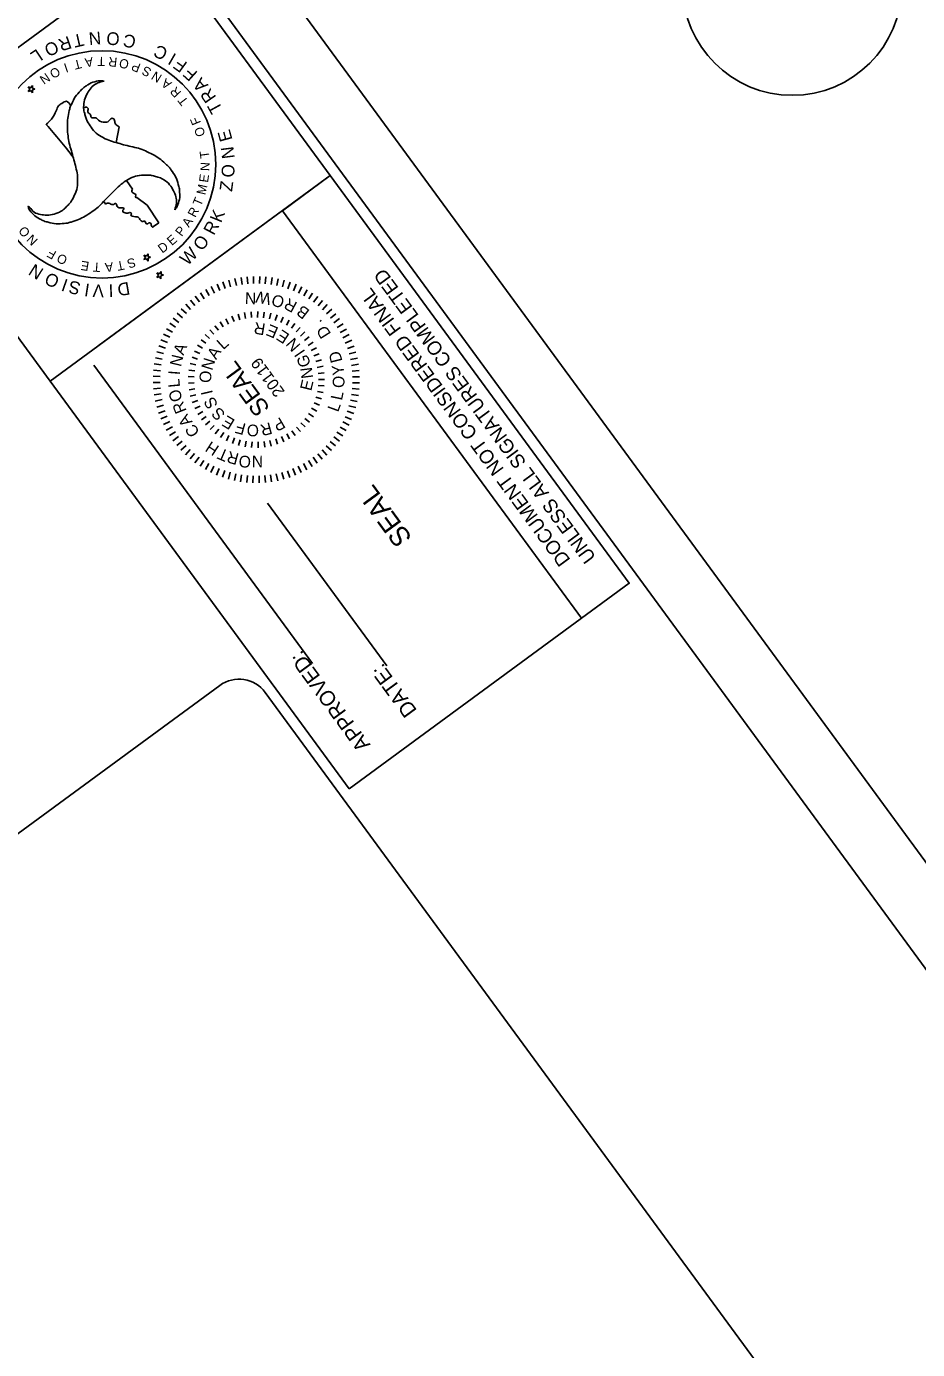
# Model space of a CAD drawing. Extents: x 719153 to 721402, y 581205 to 583188.
# Drawn here: x 720458.9 to 720670.5, y 582492.9 to 582807 of the extents above; entities that cross this region are included whole.
import ezdxf

# ---------------------------------------------------------------- set-up
doc = ezdxf.new("R2010")
doc.units = 0
for name, color, linetype in [('Old_Level_21', 7, 'Continuous'), ('Old_Level_50', 7, 'Continuous'), ('Old_Level_52', 7, 'Continuous'), ('Prop RDY Alternate Text Blue', 7, 'Continuous'), ('Scratch_Level_9', 7, 'Continuous'), ('Sheet Plot Border Inside CELL', 7, 'Continuous'), ('Sheet Plot Border Outside CELL', 7, 'Continuous'), ('Sheet Sticker Incomplete CELL', 7, 'Continuous'), ('Typical Terminator CELL', 7, 'Continuous')]:
    doc.layers.add(name, color=color, linetype=linetype)

msp = doc.modelspace()

# ---------------------------------------------------------------- linework, layer by layer
at = {"layer": 'Old_Level_21'}
for p, q in [((720519.64, 582763.23), (720531.01, 582771.57)), ((720531.01, 582771.57), (720602, 582674.8)), ((720590.64, 582666.46), (720519.64, 582763.23)), ((720602, 582674.8), (720590.64, 582666.46))]:
    msp.add_line(p, q, dxfattribs=at)
at = {"layer": 'Old_Level_50'}
msp.add_lwpolyline([(721009.35, 582149.27), (720410.24, 582965.86), (719878.1, 582575.44), (720477.21, 581758.85)], close=True, dxfattribs=at)
at = {"layer": 'Old_Level_52'}
msp.add_circle((720476.81, 582774.23), 26.98, dxfattribs=at)
at = {"layer": 'Scratch_Level_9'}
for p, q in [((720459.26, 582792.62), (720459.64, 582792.09)), ((720459.88, 582792.42), (720459.26, 582792.62)), ((720459.64, 582792.09), (720459.29, 582791.56)), ((720460.27, 582792.95), (720459.88, 582792.42)), ((720460.28, 582792.29), (720460.27, 582792.95)), ((720460.27, 582791.9), (720460.88, 582792.11)), ((720460.88, 582792.11), (720460.28, 582792.29)), ((720459.29, 582791.56), (720459.88, 582791.76)), ((720459.88, 582791.76), (720460.27, 582791.24)), ((720460.27, 582791.24), (720460.27, 582791.9)), ((720480.13, 582779.41), (720480.86, 582783.15)), ((720484.06, 582768.35), (720482.58, 582770.4)), ((720485.1, 582766.36), (720487.49, 582764.53)), ((720487.49, 582764.53), (720490.32, 582760.36)), ((720490.32, 582760.36), (720489.01, 582759.46)), ((720486.72, 582752.66), (720487.1, 582752.14)), ((720487.34, 582752.46), (720486.72, 582752.66)), ((720487.1, 582752.14), (720486.75, 582751.61)), ((720486.75, 582751.61), (720487.35, 582751.81)), ((720487.74, 582752.99), (720487.34, 582752.46)), ((720487.35, 582751.81), (720487.73, 582751.28)), ((720487.73, 582751.94), (720488.35, 582752.16)), ((720487.73, 582751.28), (720487.73, 582751.94)), ((720487.74, 582752.33), (720487.74, 582752.99)), ((720488.35, 582752.16), (720487.74, 582752.33)), ((720490.42, 582748.26), (720489.79, 582748.46)), ((720489.79, 582748.46), (720490.18, 582747.94)), ((720490.42, 582748.26), (720489.79, 582748.46)), ((720490.81, 582748.79), (720490.42, 582748.26)), ((720490.81, 582748.79), (720490.42, 582748.26)), ((720490.81, 582748.13), (720490.81, 582748.79)), ((720490.81, 582748.13), (720490.81, 582748.79)), ((720491.42, 582747.95), (720490.81, 582748.13)), ((720490.18, 582747.94), (720489.82, 582747.4)), ((720489.82, 582747.4), (720490.42, 582747.61)), ((720490.42, 582747.61), (720490.8, 582747.08)), ((720490.8, 582747.74), (720491.42, 582747.95)), ((720490.8, 582747.08), (720490.8, 582747.74))]:
    msp.add_line(p, q, dxfattribs=at)
for start, end in [(37.4702, 41.5902), (31.9452, 32.2429)]:
    msp.add_arc((720358.92, 582690.78), 139.92, start, end, dxfattribs=at)
for points in [[(720459.18, 582764.21), (720459.24, 582764.2), (720460.39, 582763.12), (720461.8, 582762.42), (720463.33, 582762.2), (720465, 582762.29), (720466.68, 582762.88), (720467.75, 582763.57), (720468.18, 582764.02), (720468.95, 582764.77), (720469.49, 582765.46), (720470.3, 582767), (720470.9, 582768.73), (720471, 582770.69), (720471, 582770.85), (720470.8, 582772.62), (720470.36, 582774.43), (720469.9, 582776.13), (720469.39, 582777.9), (720468.93, 582779.67), (720468.69, 582781.41), (720468.57, 582783.43), (720468.67, 582785.16), (720469.03, 582786.98), (720469.25, 582787.86), (720469.6, 582788.58), (720470.45, 582790.28), (720471.68, 582791.7), (720472.51, 582792.49), (720473.31, 582793.03), (720473.44, 582793.13), (720475.09, 582793.84), (720476.75, 582794.08), (720477.3, 582794.01)], [(720477.3, 582794.01), (720475.8, 582793.55), (720474.5, 582792.69), (720473.54, 582791.47), (720472.78, 582789.97), (720472.46, 582788.23), (720472.51, 582786.96), (720472.69, 582786.35), (720472.93, 582785.33), (720473.3, 582784.5), (720474.19, 582783.04), (720475.42, 582781.64), (720477.05, 582780.58), (720477.19, 582780.5), (720478.84, 582779.8), (720480.61, 582779.27), (720482.32, 582778.79), (720484.11, 582778.37), (720485.89, 582777.9), (720487.51, 582777.22), (720489.31, 582776.31), (720490.75, 582775.35), (720492.15, 582774.14), (720492.81, 582773.5), (720493.25, 582772.85), (720494.29, 582771.27), (720494.92, 582769.48), (720495.18, 582768.39), (720495.24, 582767.42), (720495.26, 582767.25), (720495.07, 582765.47), (720494.45, 582763.92), (720494.1, 582763.44)], [(720469.37, 582788.14), (720468.35, 582789.22), (720467.27, 582788.71), (720466.47, 582788.14), (720465.92, 582786.97), (720464.78, 582785), (720463.56, 582783.65)], [(720480.86, 582783.15), (720480.01, 582783.79), (720479.77, 582784.67), (720479.58, 582785.03), (720479.17, 582785.16), (720478.21, 582784.32), (720477.56, 582784.21), (720475.93, 582784.71), (720475.28, 582785.28), (720474.28, 582785.33), (720474.14, 582785.54), (720474.09, 582785.99), (720473.44, 582786.58), (720473.48, 582787.48), (720473.21, 582787.78), (720472.5, 582787.67)], [(720494.1, 582763.44), (720494.45, 582765), (720494.36, 582766.55), (720493.78, 582767.98), (720492.86, 582769.41), (720491.52, 582770.56), (720490.37, 582771.14), (720489.78, 582771.3), (720488.75, 582771.58), (720487.88, 582771.68), (720486.14, 582771.65), (720484.33, 582771.28), (720482.6, 582770.41), (720482.46, 582770.32), (720481.01, 582769.24), (720479.69, 582767.97), (720478.43, 582766.72), (720477.15, 582765.39), (720475.87, 582764.09), (720474.47, 582763.02), (720472.78, 582761.92), (720471.22, 582761.14), (720469.46, 582760.54), (720468.6, 582760.3), (720467.81, 582760.23), (720465.9, 582760.13), (720464.05, 582760.48), (720462.97, 582760.8), (720462.11, 582761.22), (720461.96, 582761.29), (720460.5, 582762.35), (720459.46, 582763.66), (720459.24, 582764.2)], [(720484.06, 582768.35), (720483.87, 582767.95), (720484.01, 582767.55), (720484.58, 582767.27), (720484.81, 582766.94), (720484.8, 582766.37), (720485.1, 582766.36)], [(720489.01, 582759.46), (720488.91, 582759.33), (720488.62, 582759.45), (720488.42, 582760.23), (720487.94, 582760.34), (720487.69, 582760.14), (720487.25, 582760.19), (720487.03, 582760.66), (720486.3, 582760.69), (720485.95, 582760.96), (720485.42, 582761.69), (720483.93, 582761.92), (720483.61, 582762.23), (720483.77, 582762.5), (720483.65, 582762.75), (720482.66, 582762.61), (720482.5, 582762.63), (720481.74, 582763.09), (720481.75, 582763.37), (720482.02, 582763.65), (720482, 582763.79), (720481.69, 582763.9), (720481.09, 582763.92), (720480.4, 582764.25), (720480.02, 582764.94), (720479.42, 582764.67), (720478.39, 582765.05), (720477.98, 582764.98), (720477.65, 582764.8)]]:
    msp.add_spline(points, degree=3, dxfattribs=at)
at = {"layer": 'Sheet Plot Border Inside CELL'}
msp.add_lwpolyline([(719899.07, 582572.22), (720431.46, 581846.57), (720939.41, 582219.25), (720407.02, 582944.89)], close=True, dxfattribs=at)
at = {"layer": 'Sheet Plot Border Outside CELL'}
for p, q in [((720475.86, 582731.11), (720531, 582771.57)), ((720526.81, 582655.76), (720474.87, 582726.55)), ((720544.4, 582655.18), (720516.08, 582693.78))]:
    msp.add_line(p, q, dxfattribs=at)
for points in [[(720340.26, 582892.08), (720424.03, 582777.92), (720490.54, 582826.72), (720406.78, 582940.89)], [(720464.49, 582722.76), (720424.03, 582777.92), (720490.54, 582826.72), (720531.01, 582771.57)], [(720535.49, 582625.99), (720464.49, 582722.76), (720531.01, 582771.57), (720602, 582674.8)]]:
    msp.add_lwpolyline(points, close=True, dxfattribs=at)
msp.add_circle((720640.7, 582816.63), 26.01, dxfattribs=at)
at = {"layer": 'Sheet Sticker Incomplete CELL'}
for p, q in [((720116.85, 582365.91), (720504.77, 582650.51)), ((720818.48, 582236), (720515.57, 582648.85))]:
    msp.add_line(p, q, dxfattribs=at)
msp.add_arc((720509.34, 582644.28), 7.73, 36.2666, 126.2666, dxfattribs=at)
at = {"layer": 'Typical Terminator CELL'}
for p, q in [((720502.76, 582745.2), (720503.48, 582743.69)), ((720504.11, 582745.8), (720504.75, 582744.26)), ((720505.5, 582746.33), (720506.04, 582744.74)), ((720506.91, 582746.76), (720507.35, 582745.15)), ((720508.35, 582747.11), (720508.7, 582745.48)), ((720509.81, 582747.38), (720510.06, 582745.72)), ((720511.28, 582747.55), (720511.43, 582745.89)), ((720512.76, 582747.64), (720512.8, 582745.97)), ((720514.24, 582747.63), (720514.18, 582745.96)), ((720515.72, 582747.54), (720515.56, 582745.88)), ((720517.19, 582747.36), (720516.93, 582745.71)), ((720518.64, 582747.09), (720518.29, 582745.46)), ((720520.08, 582746.73), (720519.63, 582745.12)), ((720521.5, 582746.29), (720520.95, 582744.71)), ((720522.88, 582745.76), (720522.24, 582744.22)), ((720524.23, 582745.15), (720523.49, 582743.65)), ((720497.78, 582742), (720498.85, 582740.71)), ((720498.95, 582742.91), (720499.94, 582741.56)), ((720500.17, 582743.75), (720501.08, 582742.34)), ((720501.44, 582744.51), (720502.26, 582743.06)), ((720525.54, 582744.45), (720524.71, 582743)), ((720526.81, 582743.69), (720525.9, 582742.28)), ((720528.02, 582742.84), (720527.03, 582741.5)), ((720529.19, 582741.93), (720528.11, 582740.65)), ((720494.64, 582738.87), (720495.92, 582737.79)), ((720495.62, 582739.97), (720496.84, 582738.83)), ((720496.67, 582741.02), (720497.81, 582739.8)), ((720509.14, 582738.7), (720509.51, 582737.36)), ((720510.66, 582739.04), (720510.9, 582737.67)), ((720512.21, 582739.24), (720512.32, 582737.85)), ((720513.77, 582739.28), (720513.74, 582737.89)), ((720515.33, 582739.17), (720515.17, 582737.79)), ((720516.87, 582738.92), (720516.57, 582737.56)), ((720530.29, 582740.94), (720529.15, 582739.73)), ((720531.34, 582739.89), (720530.12, 582738.75)), ((720532.32, 582738.78), (720531.03, 582737.71)), ((720492.88, 582736.49), (720494.28, 582735.58)), ((720493.72, 582737.7), (720495.07, 582736.71)), ((720503.58, 582735.93), (720504.43, 582734.83)), ((720504.86, 582736.82), (720505.6, 582735.64)), ((720506.8, 582736.32), (720506.18, 582737.56)), ((720507.65, 582738.22), (720508.15, 582736.92)), ((720518.38, 582738.51), (720517.95, 582737.19)), ((720519.84, 582737.97), (720519.29, 582736.68)), ((720521.24, 582737.28), (720520.57, 582736.06)), ((720522.58, 582736.46), (720521.79, 582735.31)), ((720523.82, 582735.51), (720522.92, 582734.44)), ((720533.23, 582737.61), (720531.88, 582736.62)), ((720534.07, 582736.39), (720532.66, 582735.48)), ((720490.8, 582732.56), (720492.35, 582731.92)), ((720491.42, 582733.91), (720492.92, 582733.17)), ((720492.11, 582735.22), (720493.56, 582734.39)), ((720500.33, 582732.57), (720501.46, 582731.76)), ((720501.3, 582733.8), (720502.35, 582732.88)), ((720502.39, 582734.92), (720503.34, 582733.9)), ((720524.97, 582734.46), (720523.97, 582733.48)), ((720526.01, 582733.29), (720524.92, 582732.42)), ((720534.83, 582735.12), (720533.37, 582734.3)), ((720535.52, 582733.81), (720534.01, 582733.08)), ((720536.12, 582732.46), (720534.58, 582731.82)), ((720489.83, 582729.76), (720491.44, 582729.31)), ((720490.28, 582731.18), (720491.85, 582730.63)), ((720498.76, 582729.88), (720500.02, 582729.3)), ((720499.48, 582731.27), (720500.68, 582730.56)), ((720526.93, 582732.03), (720525.77, 582731.26)), ((720527.73, 582730.69), (720526.5, 582730.04)), ((720527.1, 582728.74), (720528.4, 582729.26)), ((720536.65, 582731.07), (720535.06, 582730.53)), ((720537.08, 582729.65), (720535.47, 582729.21)), ((720489.21, 582726.87), (720490.86, 582726.61)), ((720489.47, 582728.32), (720491.11, 582727.97)), ((720497.73, 582726.93), (720499.09, 582726.6)), ((720498.17, 582728.43), (720499.49, 582727.97)), ((720528.91, 582727.8), (720527.58, 582727.4)), ((720529.29, 582726.29), (720527.92, 582726.01)), ((720537.43, 582728.21), (720535.8, 582727.87)), ((720537.7, 582726.76), (720536.04, 582726.51)), ((720488.93, 582723.92), (720490.6, 582723.87)), ((720489.02, 582725.4), (720490.69, 582725.24)), ((720497.29, 582723.84), (720498.69, 582723.78)), ((720497.44, 582725.4), (720498.82, 582725.2)), ((720529.52, 582724.74), (720528.14, 582724.6)), ((720529.6, 582723.18), (720528.21, 582723.18)), ((720537.87, 582725.28), (720536.21, 582725.14)), ((720537.96, 582723.81), (720536.29, 582723.76)), ((720488.93, 582722.44), (720490.6, 582722.48)), ((720489.01, 582720.96), (720490.68, 582721.11)), ((720497.3, 582722.28), (720498.69, 582722.35)), ((720497.46, 582720.73), (720498.83, 582720.93)), ((720529.32, 582720.08), (720527.95, 582720.34)), ((720529.54, 582721.62), (720528.15, 582721.75)), ((720537.86, 582720.85), (720536.2, 582721)), ((720537.95, 582722.33), (720536.28, 582722.38)), ((720489.19, 582719.49), (720490.84, 582719.74)), ((720489.45, 582718.03), (720491.09, 582718.38)), ((720489.8, 582716.59), (720491.41, 582717.04)), ((720497.76, 582719.2), (720499.11, 582719.53)), ((720498.21, 582717.7), (720499.53, 582718.17)), ((720498.81, 582716.26), (720500.07, 582716.85)), ((720528.43, 582717.08), (720527.14, 582717.6)), ((720528.95, 582718.56), (720527.61, 582718.95)), ((720537.05, 582716.48), (720535.44, 582716.93)), ((720537.41, 582717.92), (720535.78, 582718.27)), ((720537.68, 582719.38), (720536.03, 582719.63)), ((720490.24, 582715.18), (720491.82, 582715.72)), ((720490.76, 582713.79), (720492.31, 582714.43)), ((720499.54, 582714.88), (720500.74, 582715.59)), ((720500.4, 582713.57), (720501.52, 582714.4)), ((720501.52, 582714.4), (720500.4, 582713.57)), ((720526.08, 582713.05), (720524.99, 582713.92)), ((720527, 582714.32), (720525.83, 582715.07)), ((720527.78, 582715.66), (720526.55, 582716.31)), ((720536.08, 582713.68), (720534.54, 582714.33)), ((720536.61, 582715.07), (720535.03, 582715.62)), ((720491.37, 582712.44), (720492.87, 582713.17)), ((720492.05, 582711.12), (720493.51, 582711.94)), ((720492.82, 582709.85), (720494.22, 582710.76)), ((720501.38, 582712.36), (720502.42, 582713.29)), ((720502.48, 582711.25), (720503.42, 582712.27)), ((720503.67, 582710.24), (720504.52, 582711.35)), ((720504.96, 582709.36), (720505.7, 582710.55)), ((720522.67, 582709.85), (720521.88, 582711)), ((720523.91, 582710.81), (720523.01, 582711.87)), ((720525.05, 582711.88), (720524.05, 582712.84)), ((720534.01, 582709.76), (720532.6, 582710.67)), ((720534.77, 582711.03), (720533.32, 582711.85)), ((720535.47, 582712.33), (720533.97, 582713.07)), ((720493.65, 582708.63), (720495, 582709.62)), ((720494.57, 582707.46), (720495.85, 582708.53)), ((720495.55, 582706.35), (720496.77, 582707.49)), ((720506.33, 582708.61), (720506.95, 582709.86)), ((720507.77, 582707.99), (720508.26, 582709.29)), ((720509.25, 582707.51), (720509.62, 582708.86)), ((720510.78, 582707.18), (720511.01, 582708.55)), ((720512.33, 582707), (720512.43, 582708.39)), ((720513.89, 582706.96), (720513.86, 582708.36)), ((720515.45, 582707.08), (720515.28, 582708.47)), ((720516.99, 582707.35), (720516.68, 582708.71)), ((720518.49, 582707.77), (720518.06, 582709.09)), ((720519.95, 582708.33), (720519.39, 582709.6)), ((720521.35, 582709.03), (720520.67, 582710.24)), ((720531.26, 582706.27), (720530.05, 582707.42)), ((720532.24, 582707.38), (720530.97, 582708.45)), ((720533.16, 582708.54), (720531.82, 582709.54)), ((720496.59, 582705.3), (720497.74, 582706.52)), ((720497.7, 582704.32), (720498.77, 582705.6)), ((720498.86, 582703.4), (720499.86, 582704.75)), ((720527.93, 582703.33), (720526.94, 582704.68)), ((720529.1, 582704.25), (720528.03, 582705.53)), ((720530.21, 582705.23), (720529.07, 582706.45)), ((720500.08, 582702.56), (720500.99, 582703.96)), ((720501.34, 582701.79), (720502.17, 582703.24)), ((720502.65, 582701.1), (720503.39, 582702.6)), ((720504, 582700.48), (720504.65, 582702.03)), ((720505.39, 582699.96), (720505.94, 582701.54)), ((720506.8, 582699.51), (720507.25, 582701.12)), ((720519.97, 582699.48), (720519.53, 582701.09)), ((720521.39, 582699.92), (720520.84, 582701.5)), ((720522.78, 582700.44), (720522.14, 582701.99)), ((720524.13, 582701.05), (720523.4, 582702.55)), ((720525.44, 582701.73), (720524.62, 582703.19)), ((720526.71, 582702.5), (720525.8, 582703.9)), ((720508.24, 582699.16), (720508.59, 582700.79)), ((720509.7, 582698.89), (720509.95, 582700.54)), ((720511.17, 582698.7), (720511.32, 582700.37)), ((720512.65, 582698.61), (720512.7, 582700.28)), ((720514.13, 582698.61), (720514.08, 582700.28)), ((720515.6, 582698.69), (720515.46, 582700.36)), ((720517.08, 582698.87), (720516.83, 582700.52)), ((720518.53, 582699.13), (720518.19, 582700.77))]:
    msp.add_line(p, q, dxfattribs=at)

# ---------------------------------------------------------------- texts
at = {"layer": 'Old_Level_21'}
for s, p in [('UNLESS ALL SIGNATURES COMPLETED', (720594.22, 582680.99)), ('DOCUMENT NOT CONSIDERED FINAL', (720588.16, 582680.32))]:
    msp.add_text(s, height=3.3, rotation=126.2667, dxfattribs=at).set_placement(p)
at = {"layer": 'Old_Level_52'}
for s, rotation, p in [('R', 199.0185, (720468.89, 582804.77)), ('T', 193.1477, (720472.05, 582805.42)), ('N', 185.1586, (720476.43, 582805.78)), ('O', 176.7193, (720481.07, 582805.49)), ('C', 169.3474, (720485.05, 582804.69)), ('L', 213.6957, (720461.41, 582801.77)), ('O', 205.2563, (720465.61, 582803.73)), ('C', 154.27, (720492.69, 582801.5)), ('I', 150.0169, (720494.67, 582800.25)), ('F', 144.0293, (720497.28, 582798.24)), ('F', 138.0417, (720499.68, 582795.97)), ('A', 131.0701, (720502.15, 582793.04)), ('R', 124.8323, (720504.04, 582790.17)), ('T', 118.9615, (720505.53, 582787.31)), ('E', 105.2183, (720507.81, 582780.11)), ('N', 97.2293, (720508.33, 582775.74)), ('O', 88.79, (720508.21, 582771.1)), ('Z', 82.4354, (720507.67, 582767.64)), ('R', 61.8207, (720503.38, 582757.2)), ('K', 68.0585, (720505.07, 582760.19)), ('W', 44.4167, (720497.07, 582750.03)), ('O', 53.3814, (720500.59, 582753.48))]:
    msp.add_text(s, height=3.02, rotation=rotation, dxfattribs=at).set_placement(p)
at = {"layer": 'Prop RDY Alternate Text Blue'}
msp.add_text('SEAL', height=4.687, rotation=126.2667, dxfattribs=at).set_placement((720550.6, 582685.58))
at = {"layer": 'Scratch_Level_9'}
for s, height, rotation, p in [('T', 2.18, 193.9593, (720471.62, 582799.24)), ('A', 2.18, 188.8812, (720474.51, 582799.7)), ('T', 2.18, 178.725, (720477.56, 582799.74)), ('R', 2.18, 173.647, (720480.52, 582799.5)), ('O', 2.18, 168.5689, (720483.35, 582798.95)), ('N', 2.18, 213.9996, (720463.52, 582796.06)), ('O', 2.18, 209.1936, (720466.1, 582797.48)), ('I', 2.18, 199.0374, (720468.3, 582798.29)), ('P', 2.18, 158.4127, (720486.16, 582797.98)), ('S', 2.18, 153.3346, (720488.74, 582796.8)), ('N', 2.18, 148.2565, (720491.22, 582795.33)), ('A', 2.18, 143.1785, (720493.51, 582793.61)), ('R', 2.18, 133.0223, (720495.76, 582791.34)), ('T', 2.18, 127.9442, (720497.46, 582789.25)), ('F', 2.18, 112.7099, (720500.35, 582784.11)), ('O', 2.18, 107.6319, (720501.38, 582781.2)), ('T', 2.18, 97.4757, (720502.35, 582775.8)), ('N', 2.18, 87.3195, (720502.29, 582772.6)), ('E', 2.18, 82.2414, (720501.97, 582769.82)), ('M', 2.18, 77.1634, (720501.31, 582766.85)), ('R', 2.18, 61.9291, (720498.94, 582761.47)), ('T', 2.18, 67.0072, (720500.26, 582764.13)), ('A', 2.18, 56.851, (720497.44, 582759.12)), ('O', 2.18, 130.2112, (720459.91, 582758.05)), ('N', 2.18, 135.2893, (720461.73, 582756.3)), ('E', 2.18, 41.6168, (720493.4, 582754.82)), ('P', 2.18, 51.7729, (720495.7, 582756.96)), ('D', 2.18, 36.5387, (720491.09, 582753.03)), ('F', 2.18, 150.5236, (720466.16, 582753.43)), ('O', 2.18, 155.6017, (720468.79, 582752.22)), ('E', 2.18, 170.8359, (720473.88, 582751.04)), ('T', 2.18, 191.1483, (720481.86, 582751.42)), ('S', 2.18, 196.2263, (720484.43, 582752.12)), ('N', 3.02, 147.8527, (720463.16, 582749.22)), ('O', 3.02, 156.3601, (720466.96, 582747.46)), ('T', 2.18, 175.914, (720476.5, 582750.84)), ('A', 2.18, 186.0702, (720479.34, 582751.01)), ('I', 3.02, 160.6475, (720468.96, 582746.79)), ('S', 3.02, 166.8515, (720471.94, 582746.1)), ('I', 3.02, 171.1388, (720474.03, 582745.8)), ('V', 3.02, 177.8473, (720477.33, 582745.66)), ('I', 3.02, 182.1346, (720479.44, 582745.78)), ('D', 3.02, 189.7257, (720483.13, 582746.36))]:
    msp.add_text(s, height=height, rotation=rotation, dxfattribs=at).set_placement(p)
at = {"layer": 'Sheet Plot Border Outside CELL'}
for s, p in [('APPROVED:  ', (720540.65, 582636.46)), ('DATE:  ', (720551.73, 582644.59))]:
    msp.add_text(s, height=3.6, rotation=126.2667, dxfattribs=at).set_placement(p)
at = {"layer": 'Typical Terminator CELL'}
for s, height, rotation, p in [('N', 2.78, 178.4207, (720513.46, 582743.78)), ('W', 2.78, 169.5381, (720517.1, 582743.55)), ('O', 2.78, 160.6554, (720520.4, 582742.58)), ('R', 2.78, 151.8328, (720523.38, 582741.33)), ('B', 2.78, 142.8303, (720526.3, 582739.48)), ('R', 2.78, 170.7785, (720515.76, 582736.38)), ('E', 2.78, 157.0075, (720518.89, 582735.38)), ('D', 2.78, 122.3036, (720531.28, 582734)), ('.', 2.78, 130.046, (720529.22, 582736.84)), ('L', 2.78, 42.0843, (720505.58, 582730.08)), ('E', 2.78, 147.0216, (720521.54, 582733.78)), ('N', 2.78, 131.6295, (720524.12, 582731.3)), ('A', 2.78, 66.7307, (720496.12, 582728.75)), ('A', 2.78, 57.3805, (720503.89, 582727.73)), ('I', 2.78, 123.9998, (720525.16, 582729.72)), ('D', 2.78, 104.5083, (720533.91, 582727.53)), ('N', 2.78, 76.4983, (720495.55, 582726.05)), ('N', 2.78, 72.6768, (720502.95, 582725.15)), ('SEAL', 4.179, 126.2136, (720516.85, 582716.34)), ('20119', 2.784, 126.2136, (720520.31, 582720.29)), ('G', 2.78, 105.905, (720526.4, 582726.52)), ('Y', 2.78, 95.5358, (720534.35, 582724.27)), ('L', 2.78, 95.3682, (720495.34, 582721.38)), ('I', 2.78, 85.7927, (720495.31, 582724.15)), ('O', 2.78, 87.973, (720502.71, 582722.32)), ('E', 2.78, 76.2837, (720526.47, 582720.3)), ('N', 2.78, 97.1388, (720526.96, 582723.55)), ('O', 2.78, 86.8632, (720534.29, 582721.08)), ('O', 2.78, 108.5045, (720496.01, 582718.37)), ('I', 2.78, 103.2693, (720503.16, 582719.86)), ('L', 2.78, 78.2205, (720533.77, 582718.07)), ('R', 2.78, 111.5613, (720496.96, 582715.72)), ('S', 2.78, 118.5655, (720504.43, 582717.12)), ('L', 2.78, 70.1487, (720532.86, 582715.27)), ('A', 2.78, 123.5706, (720498.37, 582713.09)), ('S', 2.78, 133.8618, (720506.26, 582715.02)), ('E', 2.78, 149.158, (720508.57, 582713.47)), ('P', 2.78, 210.343, (720519.21, 582714.32)), ('C', 2.78, 123.5706, (720500.12, 582710.61)), ('F', 2.78, 164.4543, (720511.16, 582712.6)), ('O', 2.78, 179.7505, (720514.07, 582712.44)), ('R', 2.78, 195.0468, (720516.73, 582713.03)), ('H', 2.78, 147.2813, (720504.84, 582707.19)), ('T', 2.78, 156.7132, (720507.14, 582706.1)), ('R', 2.78, 164.8742, (720509.5, 582705.51)), ('O', 2.78, 177.9309, (720512.21, 582704.99)), ('N', 2.78, 179.8904, (720515.05, 582705.09))]:
    msp.add_text(s, height=height, rotation=rotation, dxfattribs=at).set_placement(p)

doc.saveas('drawing.dxf')
